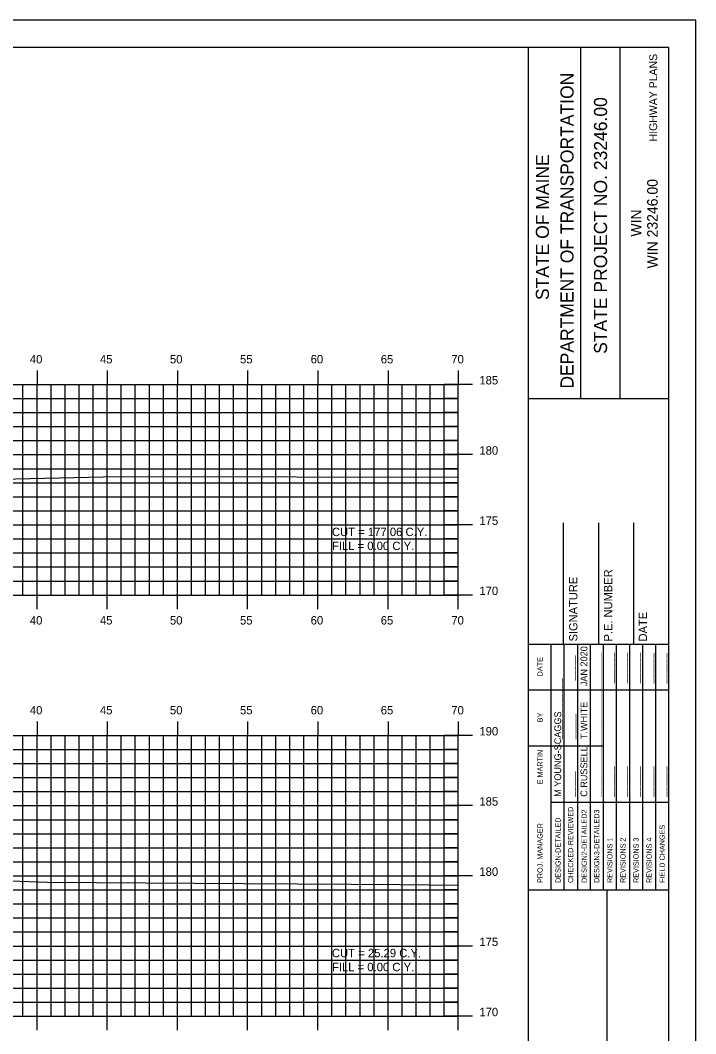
# Model space of a CAD drawing. Extents: x 1140094 to 1140264, y 608981 to 609091.
# Drawn here: x 1140215.5 to 1140263.6, y 609019.1 to 609091.3 of the extents above; entities that cross this region are included whole.
import ezdxf

# ---------------------------------------------------------------- set-up
doc = ezdxf.new("R2010")
doc.units = 0
for name, color, linetype in [('BORDER', 7, 'Continuous'), ('D_Text_Standard', 7, 'Continuous'), ('H_V ANNOTATION', 7, 'Continuous'), ('HIGHWAY_TITLE', 7, 'Continuous'), ('MAJOR', 7, 'Continuous'), ('MINOR', 7, 'Continuous'), ('PLOT BOUNDARY', 7, 'Continuous'), ('S_Roadway_Centerline', 7, 'Continuous')]:
    doc.layers.add(name, color=color, linetype=linetype)

msp = doc.modelspace()

# ---------------------------------------------------------------- linework, layer by layer
at = {"layer": 'BORDER'}
for p, q in [((1140251.732, 608984.335), (1140251.732, 609089.335)), ((1140255.46, 609064.332), (1140255.46, 609089.332)), ((1140258.255, 609064.332), (1140258.255, 609089.332)), ((1140251.733, 609064.329), (1140261.732, 609064.329)), ((1140254.232, 609046.838), (1140254.232, 609055.485)), ((1140256.732, 609046.838), (1140256.732, 609055.485)), ((1140259.232, 609046.838), (1140259.232, 609055.485)), ((1140251.732, 609046.838), (1140261.732, 609046.838)), ((1140251.732, 609029.338), (1140261.732, 609029.338)), ((1140257.323, 608994.338), (1140257.323, 609029.338))]:
    msp.add_line(p, q, dxfattribs=at)
msp.add_lwpolyline([(1140101.732, 608984.335), (1140261.732, 608984.335), (1140261.732, 609089.335), (1140101.732, 609089.335)], close=True, dxfattribs=at)
for points in [[(1140253.346, 609043.588), (1140253.346, 609046.838)], [(1140254.279, 609029.341), (1140254.279, 609046.838)], [(1140255.211, 609046.838), (1140255.211, 609029.341)], [(1140256.142, 609029.341), (1140256.142, 609046.838)], [(1140257.074, 609029.341), (1140257.074, 609046.838)], [(1140258.006, 609029.341), (1140258.006, 609046.838)], [(1140258.937, 609029.341), (1140258.937, 609046.838)], [(1140259.869, 609029.341), (1140259.869, 609046.838)], [(1140260.801, 609029.341), (1140260.801, 609046.838)], [(1140253.347, 609029.341), (1140253.347, 609046.132)], [(1140251.732, 609043.588), (1140261.732, 609043.588)], [(1140251.732, 609039.588), (1140253.347, 609039.588)], [(1140253.346, 609039.588), (1140257.073, 609039.588)], [(1140253.346, 609035.588), (1140261.732, 609035.588)]]:
    msp.add_lwpolyline(points, dxfattribs=at)
at = {"layer": 'MAJOR'}
for p, q in [((1140216.731, 609066.337), (1140216.731, 609065.335)), ((1140221.731, 609066.337), (1140221.731, 609065.335)), ((1140226.731, 609066.337), (1140226.731, 609065.335)), ((1140231.731, 609066.337), (1140231.731, 609065.335)), ((1140236.731, 609066.337), (1140236.731, 609065.335)), ((1140241.731, 609066.337), (1140241.731, 609065.335)), ((1140246.731, 609066.337), (1140246.731, 609065.335)), ((1140106.731, 609065.335), (1140246.731, 609065.335)), ((1140106.731, 609065.335), (1140246.731, 609065.335)), ((1140216.731, 609050.335), (1140216.731, 609065.335)), ((1140221.731, 609050.335), (1140221.731, 609065.335)), ((1140226.731, 609050.335), (1140226.731, 609065.335)), ((1140231.731, 609050.335), (1140231.731, 609065.335)), ((1140236.731, 609050.335), (1140236.731, 609065.335)), ((1140241.731, 609050.335), (1140241.731, 609065.335)), ((1140247.733, 609065.335), (1140245.729, 609065.335)), ((1140246.731, 609050.335), (1140246.731, 609065.335)), ((1140246.731, 609050.335), (1140246.731, 609065.335)), ((1140106.731, 609060.335), (1140246.731, 609060.335)), ((1140247.733, 609060.335), (1140245.729, 609060.335)), ((1140106.731, 609055.335), (1140246.731, 609055.335)), ((1140247.733, 609055.335), (1140245.729, 609055.335)), ((1140106.731, 609050.335), (1140246.731, 609050.335)), ((1140106.731, 609050.335), (1140246.731, 609050.335)), ((1140216.731, 609049.333), (1140216.731, 609050.335)), ((1140221.731, 609049.333), (1140221.731, 609050.335)), ((1140226.731, 609049.333), (1140226.731, 609050.335)), ((1140231.731, 609049.333), (1140231.731, 609050.335)), ((1140236.731, 609049.333), (1140236.731, 609050.335)), ((1140241.731, 609049.333), (1140241.731, 609050.335)), ((1140247.733, 609050.335), (1140245.729, 609050.335)), ((1140246.731, 609049.333), (1140246.731, 609050.335)), ((1140216.731, 609041.337), (1140216.731, 609040.335)), ((1140221.731, 609041.337), (1140221.731, 609040.335)), ((1140226.731, 609041.337), (1140226.731, 609040.335)), ((1140231.731, 609041.337), (1140231.731, 609040.335)), ((1140236.731, 609041.337), (1140236.731, 609040.335)), ((1140241.731, 609041.337), (1140241.731, 609040.335)), ((1140246.731, 609041.337), (1140246.731, 609040.335)), ((1140106.731, 609040.335), (1140246.731, 609040.335)), ((1140106.731, 609040.335), (1140246.731, 609040.335)), ((1140216.731, 609020.335), (1140216.731, 609040.335)), ((1140221.731, 609020.335), (1140221.731, 609040.335)), ((1140226.731, 609020.335), (1140226.731, 609040.335)), ((1140231.731, 609020.335), (1140231.731, 609040.335)), ((1140236.731, 609020.335), (1140236.731, 609040.335)), ((1140241.731, 609020.335), (1140241.731, 609040.335)), ((1140247.733, 609040.335), (1140245.729, 609040.335)), ((1140246.731, 609020.335), (1140246.731, 609040.335)), ((1140246.731, 609020.335), (1140246.731, 609040.335)), ((1140106.731, 609035.335), (1140246.731, 609035.335)), ((1140247.733, 609035.335), (1140245.729, 609035.335)), ((1140106.731, 609030.335), (1140246.731, 609030.335)), ((1140247.733, 609030.335), (1140245.729, 609030.335)), ((1140106.731, 609025.335), (1140246.731, 609025.335)), ((1140247.733, 609025.335), (1140245.729, 609025.335)), ((1140106.731, 609020.335), (1140246.731, 609020.335)), ((1140106.731, 609020.335), (1140246.731, 609020.335)), ((1140216.731, 609019.333), (1140216.731, 609020.335)), ((1140221.731, 609019.333), (1140221.731, 609020.335)), ((1140226.731, 609019.333), (1140226.731, 609020.335)), ((1140231.731, 609019.333), (1140231.731, 609020.335)), ((1140236.731, 609019.333), (1140236.731, 609020.335)), ((1140241.731, 609019.333), (1140241.731, 609020.335)), ((1140247.733, 609020.335), (1140245.729, 609020.335)), ((1140246.731, 609019.333), (1140246.731, 609020.335))]:
    msp.add_line(p, q, dxfattribs=at)
at = {"layer": 'MINOR'}
for p, q in [((1140215.731, 609050.335), (1140215.731, 609065.335)), ((1140217.731, 609050.335), (1140217.731, 609065.335)), ((1140218.731, 609050.335), (1140218.731, 609065.335)), ((1140219.731, 609050.335), (1140219.731, 609065.335)), ((1140220.731, 609050.335), (1140220.731, 609065.335)), ((1140222.731, 609050.335), (1140222.731, 609065.335)), ((1140223.731, 609050.335), (1140223.731, 609065.335)), ((1140224.731, 609050.335), (1140224.731, 609065.335)), ((1140225.731, 609050.335), (1140225.731, 609065.335)), ((1140227.731, 609050.335), (1140227.731, 609065.335)), ((1140228.731, 609050.335), (1140228.731, 609065.335)), ((1140229.731, 609050.335), (1140229.731, 609065.335)), ((1140230.731, 609050.335), (1140230.731, 609065.335)), ((1140232.731, 609050.335), (1140232.731, 609065.335)), ((1140233.731, 609050.335), (1140233.731, 609065.335)), ((1140234.731, 609050.335), (1140234.731, 609065.335)), ((1140235.731, 609050.335), (1140235.731, 609065.335)), ((1140237.731, 609050.335), (1140237.731, 609065.335)), ((1140238.731, 609050.335), (1140238.731, 609065.335)), ((1140239.731, 609050.335), (1140239.731, 609065.335)), ((1140240.731, 609050.335), (1140240.731, 609065.335)), ((1140242.731, 609050.335), (1140242.731, 609065.335)), ((1140243.731, 609050.335), (1140243.731, 609065.335)), ((1140244.731, 609050.335), (1140244.731, 609065.335)), ((1140245.731, 609050.335), (1140245.731, 609065.335)), ((1140106.731, 609064.335), (1140246.731, 609064.335)), ((1140246.731, 609064.335), (1140245.729, 609064.335)), ((1140106.731, 609063.335), (1140246.731, 609063.335)), ((1140246.731, 609063.335), (1140245.729, 609063.335)), ((1140106.731, 609062.335), (1140246.731, 609062.335)), ((1140246.731, 609062.335), (1140245.729, 609062.335)), ((1140106.731, 609061.335), (1140246.731, 609061.335)), ((1140246.731, 609061.335), (1140245.729, 609061.335)), ((1140106.731, 609059.335), (1140246.731, 609059.335)), ((1140246.731, 609059.335), (1140245.729, 609059.335)), ((1140106.731, 609058.335), (1140246.731, 609058.335)), ((1140246.731, 609058.335), (1140245.729, 609058.335)), ((1140106.731, 609057.335), (1140246.731, 609057.335)), ((1140246.731, 609057.335), (1140245.729, 609057.335)), ((1140106.731, 609056.335), (1140246.731, 609056.335)), ((1140246.731, 609056.335), (1140245.729, 609056.335)), ((1140106.731, 609054.335), (1140246.731, 609054.335)), ((1140246.731, 609054.335), (1140245.729, 609054.335)), ((1140106.731, 609053.335), (1140246.731, 609053.335)), ((1140246.731, 609053.335), (1140245.729, 609053.335)), ((1140106.731, 609052.335), (1140246.731, 609052.335)), ((1140246.731, 609052.335), (1140245.729, 609052.335)), ((1140106.731, 609051.335), (1140246.731, 609051.335)), ((1140246.731, 609051.335), (1140245.729, 609051.335)), ((1140215.731, 609020.335), (1140215.731, 609040.335)), ((1140217.731, 609020.335), (1140217.731, 609040.335)), ((1140218.731, 609020.335), (1140218.731, 609040.335)), ((1140219.731, 609020.335), (1140219.731, 609040.335)), ((1140220.731, 609020.335), (1140220.731, 609040.335)), ((1140222.731, 609020.335), (1140222.731, 609040.335)), ((1140223.731, 609020.335), (1140223.731, 609040.335)), ((1140224.731, 609020.335), (1140224.731, 609040.335)), ((1140225.731, 609020.335), (1140225.731, 609040.335)), ((1140227.731, 609020.335), (1140227.731, 609040.335)), ((1140228.731, 609020.335), (1140228.731, 609040.335)), ((1140229.731, 609020.335), (1140229.731, 609040.335)), ((1140230.731, 609020.335), (1140230.731, 609040.335)), ((1140232.731, 609020.335), (1140232.731, 609040.335)), ((1140233.731, 609020.335), (1140233.731, 609040.335)), ((1140234.731, 609020.335), (1140234.731, 609040.335)), ((1140235.731, 609020.335), (1140235.731, 609040.335)), ((1140237.731, 609020.335), (1140237.731, 609040.335)), ((1140238.731, 609020.335), (1140238.731, 609040.335)), ((1140239.731, 609020.335), (1140239.731, 609040.335)), ((1140240.731, 609020.335), (1140240.731, 609040.335)), ((1140242.731, 609020.335), (1140242.731, 609040.335)), ((1140243.731, 609020.335), (1140243.731, 609040.335)), ((1140244.731, 609020.335), (1140244.731, 609040.335)), ((1140245.731, 609020.335), (1140245.731, 609040.335)), ((1140106.731, 609039.335), (1140246.731, 609039.335)), ((1140246.731, 609039.335), (1140245.729, 609039.335)), ((1140106.731, 609038.335), (1140246.731, 609038.335)), ((1140246.731, 609038.335), (1140245.729, 609038.335)), ((1140106.731, 609037.335), (1140246.731, 609037.335)), ((1140246.731, 609037.335), (1140245.729, 609037.335)), ((1140106.731, 609036.335), (1140246.731, 609036.335)), ((1140246.731, 609036.335), (1140245.729, 609036.335)), ((1140106.731, 609034.335), (1140246.731, 609034.335)), ((1140246.731, 609034.335), (1140245.729, 609034.335)), ((1140106.731, 609033.335), (1140246.731, 609033.335)), ((1140246.731, 609033.335), (1140245.729, 609033.335)), ((1140106.731, 609032.335), (1140246.731, 609032.335)), ((1140246.731, 609032.335), (1140245.729, 609032.335)), ((1140106.731, 609031.335), (1140246.731, 609031.335)), ((1140246.731, 609031.335), (1140245.729, 609031.335)), ((1140106.731, 609029.335), (1140246.731, 609029.335)), ((1140246.731, 609029.335), (1140245.729, 609029.335)), ((1140106.731, 609028.335), (1140246.731, 609028.335)), ((1140246.731, 609028.335), (1140245.729, 609028.335)), ((1140106.731, 609027.335), (1140246.731, 609027.335)), ((1140246.731, 609027.335), (1140245.729, 609027.335)), ((1140106.731, 609026.335), (1140246.731, 609026.335)), ((1140246.731, 609026.335), (1140245.729, 609026.335)), ((1140106.731, 609024.335), (1140246.731, 609024.335)), ((1140246.731, 609024.335), (1140245.729, 609024.335)), ((1140106.731, 609023.335), (1140246.731, 609023.335)), ((1140246.731, 609023.335), (1140245.729, 609023.335)), ((1140106.731, 609022.335), (1140246.731, 609022.335)), ((1140246.731, 609022.335), (1140245.729, 609022.335)), ((1140106.731, 609021.335), (1140246.731, 609021.335)), ((1140246.731, 609021.335), (1140245.729, 609021.335))]:
    msp.add_line(p, q, dxfattribs=at)
at = {"layer": 'PLOT BOUNDARY'}
msp.add_lwpolyline([(1140093.638, 608981.276), (1140263.638, 608981.276), (1140263.638, 609091.276), (1140093.638, 609091.276)], close=True, dxfattribs=at)
at = {"layer": 'S_Roadway_Centerline'}
for points in [[(1140145.884, 609056.638), (1140156.704, 609056.772), (1140158.401, 609056.894), (1140164.633, 609058.607), (1140165.669, 609058.733), (1140165.972, 609058.746), (1140166.042, 609058.687), (1140166.187, 609058.687), (1140169.779, 609058.79), (1140177.071, 609059.28), (1140183.662, 609058.861), (1140188.271, 609058.728), (1140190.31, 609058.358), (1140191.022, 609058.194), (1140195.441, 609057.212), (1140195.554, 609057.192), (1140195.653, 609057.202), (1140199.545, 609058.254), (1140201.609, 609058.298), (1140221.444, 609058.751), (1140223.681, 609058.778), (1140246.731, 609058.72)], [(1140214.845, 609029.983), (1140217.475, 609029.884), (1140231.454, 609029.795), (1140239.091, 609029.739), (1140242.578, 609029.71), (1140246.731, 609029.67)]]:
    msp.add_lwpolyline(points, dxfattribs=at)

# ---------------------------------------------------------------- texts
at = {"layer": 'BORDER'}
for s, height, p in [('DEPARTMENT OF TRANSPORTATION', 0.93176, (1140254.938, 609065.041)), ('STATE PROJECT NO. 23246.00', 0.93176, (1140257.324, 609067.517)), ('STATE OF MAINE', 0.93176, (1140253.187, 609071.347)), ('WIN 23246.00', 0.74527, (1140260.927, 609073.596)), ('WIN', 0.7453, (1140259.768, 609075.865)), ('SIGNATURE', 0.5906, (1140255.212, 609047.03)), ('P.E. NUMBER', 0.59055, (1140257.692, 609047.03)), ('DATE', 0.5906, (1140260.173, 609047.03)), ('JAN 2020', 0.4845, (1140255.918, 609043.843)), ('DATE', 0.3714, (1140252.736, 609044.544)), ('_____', 0.4845, (1140254.949, 609044.243)), ('______', 0.4845, (1140256.812, 609044.063)), ('______', 0.4845, (1140257.744, 609044.065)), ('______', 0.4845, (1140258.676, 609044.067)), ('______', 0.4845, (1140259.607, 609044.067)), ('______', 0.4845, (1140260.539, 609044.036)), ('______', 0.4845, (1140261.471, 609044.036)), ('____________', 0.48455, (1140254.055, 609040.073)), ('____________', 0.48455, (1140256.812, 609040.073)), ('T.WHITE', 0.4845, (1140255.918, 609040.073)), ('BY', 0.3714, (1140252.736, 609041.273)), ('M YOUNG-SCAGGS', 0.48455, (1140254.055, 609035.961)), ('_____', 0.4845, (1140254.986, 609040.073)), ('____________', 0.48455, (1140256.812, 609035.961)), ('C.RUSSELL', 0.4845, (1140255.918, 609035.961)), ('E MARTIN', 0.3727, (1140252.736, 609036.855)), ('_____', 0.4845, (1140254.949, 609035.961)), ('______', 0.4845, (1140257.744, 609035.961)), ('______', 0.4845, (1140258.676, 609035.961)), ('______', 0.4845, (1140259.607, 609035.961)), ('______', 0.4845, (1140260.539, 609035.961)), ('______', 0.4845, (1140261.471, 609035.961)), ('CHECKED-REVIEWED', 0.37275, (1140254.913, 609029.826)), ('DESIGN2-DETAILED2', 0.37275, (1140255.882, 609029.826)), ('DESIGN3-DETAILED3', 0.37275, (1140256.776, 609029.826)), ('DESIGN-DETAILED', 0.37275, (1140254.018, 609029.826)), ('PROJ. MANAGER', 0.37275, (1140252.736, 609029.826)), ('FIELD CHANGES', 0.37275, (1140261.434, 609029.826)), ('REVISIONS 1', 0.37275, (1140257.708, 609029.826)), ('REVISIONS 2', 0.37275, (1140258.639, 609029.826)), ('REVISIONS 3', 0.37275, (1140259.571, 609029.826)), ('REVISIONS 4', 0.37275, (1140260.503, 609029.826))]:
    msp.add_text(s, height=height, rotation=90, dxfattribs=at).set_placement(p)
at = {"layer": 'D_Text_Standard'}
for s, p in [('CUT = 177.06 C.Y.', (1140237.731, 609054.535)), ('FILL = 0.00 C.Y.', (1140237.731, 609053.539)), ('CUT = 25.29 C.Y.', (1140237.731, 609024.535)), ('FILL = 0.00 C.Y.', (1140237.731, 609023.539))]:
    msp.add_text(s, height=0.6, dxfattribs=at).set_placement(p)
at = {"layer": 'H_V ANNOTATION'}
for s, p in [('40', (1140216.218, 609066.835)), ('45', (1140221.21, 609066.835)), ('50', (1140226.196, 609066.835)), ('55', (1140231.188, 609066.835)), ('60', (1140236.218, 609066.835)), ('65', (1140241.21, 609066.835)), ('70', (1140246.234, 609066.835)), ('185', (1140248.231, 609065.335)), ('180', (1140248.231, 609060.335)), ('175', (1140248.231, 609055.335)), ('170', (1140248.231, 609050.335)), ('40', (1140216.218, 609048.235)), ('45', (1140221.21, 609048.235)), ('50', (1140226.196, 609048.235)), ('55', (1140231.188, 609048.235)), ('60', (1140236.218, 609048.235)), ('65', (1140241.21, 609048.235)), ('70', (1140246.234, 609048.235)), ('40', (1140216.218, 609041.835)), ('45', (1140221.21, 609041.835)), ('50', (1140226.196, 609041.835)), ('55', (1140231.188, 609041.835)), ('60', (1140236.218, 609041.835)), ('65', (1140241.21, 609041.835)), ('70', (1140246.234, 609041.835)), ('190', (1140248.231, 609040.335)), ('185', (1140248.231, 609035.335)), ('180', (1140248.231, 609030.335)), ('175', (1140248.231, 609025.335)), ('170', (1140248.231, 609020.335))]:
    msp.add_text(s, height=0.6, dxfattribs=at).set_placement(p)
at = {"layer": 'HIGHWAY_TITLE'}
msp.add_text('HIGHWAY PLANS', height=0.55901, rotation=90, dxfattribs=at).set_placement((1140260.89, 609082.65))

doc.saveas('drawing.dxf')
